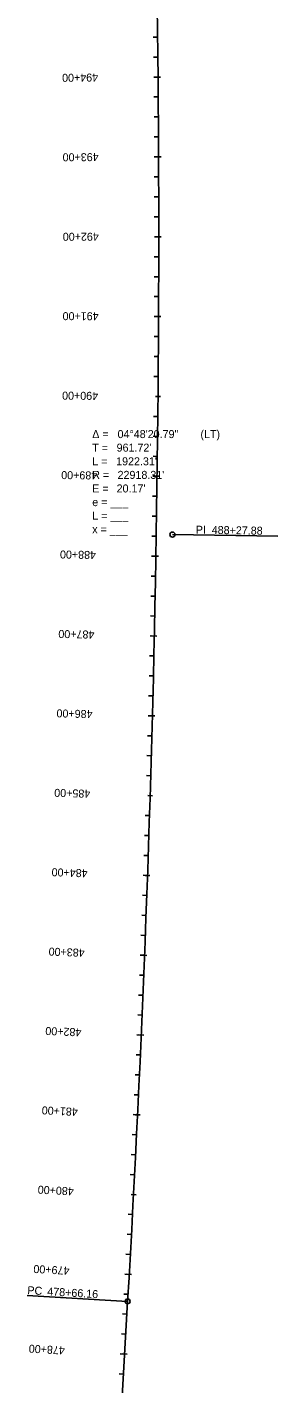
# Model space of a CAD drawing. Extents: x 23417911 to 23421158, y 6737892 to 6791804.
# Drawn here: x 23420777 to 23421090, y 6773259 to 6774957 of the extents above; entities that cross this region are included whole.
import ezdxf

# ---------------------------------------------------------------- set-up
doc = ezdxf.new("R2010")
doc.units = 0
for name, color, linetype in [('Alignment', 7, 'Continuous'), ('TextAlignment', 7, 'Continuous'), ('TextAlignmentLrg', 7, 'Continuous'), ('TextAlignmentSml', 7, 'Continuous')]:
    doc.layers.add(name, color=color, linetype=linetype)

msp = doc.modelspace()

# ---------------------------------------------------------------- linework, layer by layer
at = {"layer": 'Alignment'}
msp.add_line((23420848.9, 6772444.9), (23420902.4, 6773361.8), dxfattribs=at)
msp.add_line((23420848.9, 6772444.9), (23420902.4, 6773361.8), dxfattribs=at)
msp.add_arc((23398023, 6774696.7), 22918.3, 356.66087, 1.46665, dxfattribs=at)
msp.add_arc((23398023, 6774696.7), 22918.3, 356.66087, 1.46665, dxfattribs=at)
at = {"layer": 'TextAlignment'}
for p, q in [((23420958.4, 6774321.9), (23421090.4, 6774319.8)), ((23421090.4, 6774319.8), (23421090.4, 6774319.8)), ((23420902.4, 6773361.8), (23420776.6, 6773369.2)), ((23420776.6, 6773369.2), (23420776.6, 6773369.2))]:
    msp.add_line(p, q, dxfattribs=at)
for centre in [(23420958.4, 6774321.9), (23420902.4, 6773361.8)]:
    msp.add_circle(centre, 3.12, dxfattribs=at)
at = {"layer": 'TextAlignmentLrg'}
for p, q in [((23420940.5, 6774894.9), (23420935, 6774894.9)), ((23420941.1, 6774794.9), (23420935.6, 6774794.9)), ((23420941.3, 6774694.9), (23420935.9, 6774694.9)), ((23420941.1, 6774594.9), (23420935.6, 6774594.9)), ((23420937.4, 6774494.9), (23420943.5, 6774494.9)), ((23420939.3, 6774394.9), (23420933.9, 6774395)), ((23420937.8, 6774294.9), (23420932.3, 6774295)), ((23420935.8, 6774194.9), (23420930.4, 6774195.1)), ((23420933.4, 6774095), (23420928, 6774095.1)), ((23420927.5, 6773995.1), (23420933.6, 6773994.9)), ((23420927.3, 6773895.1), (23420921.8, 6773895.3)), ((23420923.6, 6773795.1), (23420918.1, 6773795.4)), ((23420919.4, 6773695.2), (23420914, 6773695.5)), ((23420914.8, 6773595.3), (23420909.4, 6773595.6)), ((23420906.8, 6773495.6), (23420912.9, 6773495.3)), ((23420904.4, 6773395.6), (23420898.9, 6773395.9)), ((23420898.6, 6773295.8), (23420893.1, 6773296.1))]:
    msp.add_line(p, q, dxfattribs=at)
at = {"layer": 'TextAlignmentSml'}
for p, q in [((23420940, 6774944.9), (23420934.5, 6774944.8)), ((23420940.2, 6774919.9), (23420934.8, 6774919.9)), ((23420937.4, 6774894.9), (23420943.5, 6774894.9)), ((23420940.7, 6774869.9), (23420935.2, 6774869.9)), ((23420940.8, 6774844.9), (23420935.4, 6774844.9)), ((23420941, 6774819.9), (23420935.5, 6774819.9)), ((23420938, 6774794.9), (23420944.2, 6774794.9)), ((23420941.2, 6774769.9), (23420935.7, 6774769.9)), ((23420941.3, 6774744.9), (23420935.8, 6774744.9)), ((23420941.3, 6774719.9), (23420935.8, 6774719.9)), ((23420938.3, 6774694.9), (23420944.4, 6774694.9)), ((23420941.3, 6774669.9), (23420935.8, 6774669.9)), ((23420941.3, 6774644.9), (23420935.8, 6774644.9)), ((23420941.2, 6774619.9), (23420935.7, 6774619.9)), ((23420938, 6774594.9), (23420944.1, 6774594.9)), ((23420941, 6774569.9), (23420935.5, 6774569.9)), ((23420940.8, 6774544.9), (23420935.4, 6774544.9)), ((23420940.6, 6774519.9), (23420935.2, 6774520)), ((23420937.4, 6774494.9), (23420943.5, 6774494.9)), ((23420940.2, 6774469.9), (23420934.7, 6774470)), ((23420939.9, 6774444.9), (23420934.5, 6774445)), ((23420939.6, 6774419.9), (23420934.2, 6774420)), ((23420936.3, 6774395), (23420942.4, 6774394.9)), ((23420939, 6774369.9), (23420933.5, 6774370)), ((23420938.6, 6774344.9), (23420933.2, 6774345)), ((23420938.2, 6774319.9), (23420932.8, 6774320)), ((23420934.7, 6774295), (23420940.9, 6774294.9)), ((23420937.3, 6774269.9), (23420931.9, 6774270)), ((23420936.9, 6774244.9), (23420931.4, 6774245)), ((23420936.4, 6774219.9), (23420930.9, 6774220.1)), ((23420932.8, 6774195), (23420938.9, 6774194.9)), ((23420935.3, 6774170), (23420929.8, 6774170.1)), ((23420934.7, 6774145), (23420929.2, 6774145.1)), ((23420934.1, 6774120), (23420928.6, 6774120.1)), ((23420930.4, 6774095.1), (23420936.5, 6774094.9)), ((23420932.7, 6774070), (23420927.3, 6774070.1)), ((23420932, 6774045), (23420926.6, 6774045.2)), ((23420931.3, 6774020), (23420925.9, 6774020.2)), ((23420927.5, 6773995.1), (23420933.6, 6773994.9)), ((23420929.8, 6773970), (23420924.3, 6773970.2)), ((23420929, 6773945), (23420923.5, 6773945.2)), ((23420928.2, 6773920.1), (23420922.7, 6773920.2)), ((23420924.2, 6773895.2), (23420930.3, 6773895)), ((23420926.4, 6773870.1), (23420920.9, 6773870.3)), ((23420925.5, 6773845.1), (23420920, 6773845.3)), ((23420924.5, 6773820.1), (23420919.1, 6773820.3)), ((23420920.5, 6773795.3), (23420926.6, 6773795)), ((23420922.6, 6773770.2), (23420917.1, 6773770.4)), ((23420921.6, 6773745.2), (23420916.1, 6773745.4)), ((23420920.5, 6773720.2), (23420915, 6773720.4)), ((23420916.4, 6773695.4), (23420922.5, 6773695.1)), ((23420918.3, 6773670.3), (23420912.9, 6773670.5)), ((23420917.2, 6773645.3), (23420911.7, 6773645.5)), ((23420916, 6773620.3), (23420910.6, 6773620.6)), ((23420911.8, 6773595.5), (23420917.9, 6773595.2)), ((23420913.6, 6773570.4), (23420908.2, 6773570.6)), ((23420912.4, 6773545.4), (23420906.9, 6773545.7)), ((23420911.1, 6773520.4), (23420905.7, 6773520.7)), ((23420906.8, 6773495.6), (23420912.9, 6773495.3)), ((23420908.5, 6773470.5), (23420903, 6773470.8)), ((23420907.1, 6773445.5), (23420901.7, 6773445.8)), ((23420905.8, 6773420.6), (23420900.3, 6773420.9)), ((23420901.3, 6773395.8), (23420907.4, 6773395.4)), ((23420902.9, 6773370.7), (23420897.5, 6773371)), ((23420901.5, 6773345.7), (23420896, 6773346)), ((23420900, 6773320.7), (23420894.6, 6773321.1)), ((23420895.5, 6773296), (23420901.6, 6773295.6)), ((23420897.1, 6773270.8), (23420891.6, 6773271.1))]:
    msp.add_line(p, q, dxfattribs=at)

# ---------------------------------------------------------------- texts
at = {"layer": 'TextAlignment'}
for s, p in [('Δ = ', (23420858.1, 6774442.8)), ('04°48\'20.79"', (23420889.8, 6774442.8)), (' (LT)', (23420989.8, 6774442.8)), ('T = ', (23420858.1, 6774425.8)), ("961.72'", (23420888.6, 6774425.8)), ('L = ', (23420858.1, 6774408.7)), ("1922.31'", (23420888, 6774408.7)), ('R = ', (23420858.1, 6774391.7)), ("22918.31'", (23420889.8, 6774391.7)), ('E = ', (23420858.1, 6774374.7)), ("20.17'", (23420888.6, 6774374.7)), ('e = ___ ', (23420858.1, 6774357.6)), ('L = ___', (23420858.1, 6774340.6)), ('x = ___', (23420858.1, 6774323.6))]:
    msp.add_text(s, height=10.02, dxfattribs=at).set_placement(p)
for s, rotation, p in [('PI ', 359.0638, (23420987.6, 6774323.1)), ('488+27.88', 359.0638, (23421007.6, 6774322.8)), ('PC', 356.6609, (23420776.7, 6773370.9)), ('478+66.16', 356.6609, (23420801.6, 6773369.4))]:
    msp.add_text(s, height=10.02, rotation=rotation, dxfattribs=at).set_placement(p)
at = {"layer": 'TextAlignmentLrg'}
for s, rotation, p in [('490+00', 179.4955, (23420865.5, 6774500.6)), ('485+00', 178.2455, (23420855.8, 6774002.3)), ('480+00', 176.9955, (23420835.2, 6773504.4))]:
    msp.add_text(s, height=10.02, rotation=rotation, dxfattribs=at).set_placement(p)
at = {"layer": 'TextAlignmentSml'}
for s, rotation, p in [('494+00', 180.4955, (23420865.4, 6774899.3)), ('493+00', 180.2455, (23420866.1, 6774799.6)), ('492+00', 179.9955, (23420866.3, 6774699.9)), ('491+00', 179.7455, (23420866.1, 6774600.3)), ('490+00', 179.4955, (23420865.5, 6774500.6)), ('489+00', 179.2455, (23420864.4, 6774400.9)), ('488+00', 178.9955, (23420862.9, 6774301.3)), ('487+00', 178.7455, (23420860.9, 6774201.6)), ('486+00', 178.4955, (23420858.6, 6774102)), ('485+00', 178.2455, (23420855.8, 6774002.3)), ('484+00', 177.9955, (23420852.5, 6773902.7)), ('483+00', 177.7455, (23420848.8, 6773803.1)), ('482+00', 177.4955, (23420844.7, 6773703.5)), ('481+00', 177.2455, (23420840.2, 6773603.9)), ('480+00', 176.9955, (23420835.2, 6773504.4)), ('479+00', 176.7455, (23420829.8, 6773404.9)), ('478+00', 176.6609, (23420824, 6773305.1))]:
    msp.add_text(s, height=10.02, rotation=rotation, dxfattribs=at).set_placement(p)

doc.saveas('drawing.dxf')
